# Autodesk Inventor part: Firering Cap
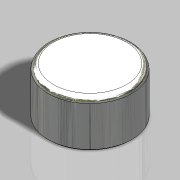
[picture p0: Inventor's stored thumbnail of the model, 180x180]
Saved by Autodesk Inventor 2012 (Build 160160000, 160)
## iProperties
Company: MH Vaaben Teknik
Category: Sten MK II Magazine
Created: 2011-12
Part Number: Firering Cap
Material: Steel, Mild
Document SubType Name: Modeling
Designer: Michael Høgh
Density: 7.86 g/cm^3
Mass: 0.0558126 g
Surface Area: 0.730789 cm^2
Volume: 0.00710084 cm^3
Project: Sten MK II
Engineer: MH Vaaben Teknik
Author: Michael Høgh
Title: Firering Cap
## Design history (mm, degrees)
sketch "Sketch1"
  geometry: C1 r 2 at (0, 0); 1 further point
  constraints: 1 centre point, 1 coincident
  dimensions: "d0" = 4 diameter of C1
extrude "Extrusion1" new body sketch "Sketch1" distance "d1" = 2.2; taper "d2" = 0 deg
fillet "Fillet1" dims "d3" = 0.25
shell "Shell1" dims "d4" = 0.2
chamfer "Chamfer1" distance "d5" = 0.05; stored, may be unused: second distance "d6" = 2, angle "d7" = 45 deg
body "Solid1"
